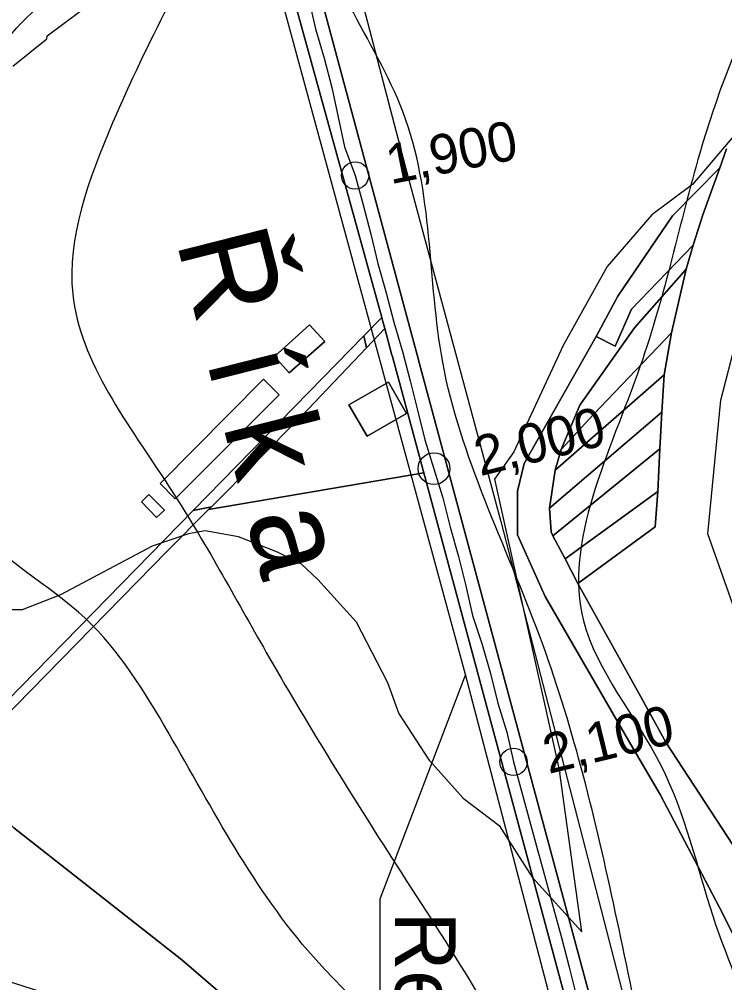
# Model space of a CAD drawing. Extents: x -510989 to -501240, y -1184665 to -1176098.
# Drawn here: x -504846 to -504613.7, y -1181469.7 to -1181152.6 of the extents above; entities that cross this region are included whole.
import ezdxf

# ---------------------------------------------------------------- set-up
doc = ezdxf.new("R2010")
doc.units = 0
for name, color, linetype in [('NAVRH_revitalizace_toku', 7, 'Continuous'), ('orna_puda', 7, 'Continuous'), ('ostatni_plocha_x_draha', 7, 'Continuous'), ('ostatni_plocha_x_jina_plocha', 7, 'Continuous'), ('ostatni_plocha_x_ostatni_komunikace', 7, 'Continuous'), ('ostatni_plocha_x_sportoviste_a_rekr_plocha', 7, 'Continuous'), ('STAV_zaplavove_uzemi', 7, 'Continuous'), ('trasovani_toku', 7, 'Continuous'), ('vodni_plocha_x_vodni_tok_v_koryt_prir_n_upr', 7, 'Continuous'), ('vrstevnice_01', 7, 'Continuous'), ('vrstevnice_02', 7, 'Continuous'), ('zastavena_plocha_a_nadvori', 7, 'Continuous')]:
    doc.layers.add(name, color=color, linetype=linetype)

msp = doc.modelspace()

# ---------------------------------------------------------------- linework, layer by layer
at = {"layer": 'NAVRH_revitalizace_toku'}
for points in [[(-504182.04, -1180792.04), (-504204.87, -1180813.12), (-504441.3, -1180893.49), (-504535.64, -1180920.73), (-504547.6, -1180927.38), (-504622.01, -1180977.87), (-504664.53, -1181014.41), (-504691.11, -1181051.62), (-504730.92, -1181097.66), (-504738.16, -1181127.41), (-504718.87, -1181201.36), (-504687.51, -1181317.93), (-504646.6, -1181475.99), (-504595.04, -1181660.81)], [(-504619.38, -1181665.94), (-504652.45, -1181546.29), (-504699.14, -1181368.28), (-504767.85, -1181115.82)], [(-504699.14, -1181368.28), (-504727.32, -1181442.23), (-504727.15, -1181617.42)]]:
    msp.add_lwpolyline(points, dxfattribs=at)
at = {"layer": 'orna_puda'}
for points in [[(-504609.62, -1181654.37), (-504714.66, -1181264.33), (-504714.68, -1181264.25), (-504716.76, -1181256.52), (-504751.58, -1181127.22), (-504752.67, -1181115.82), (-504749.63, -1181100.59), (-504733.91, -1181066.63), (-504677.14, -1181000.88), (-504645.58, -1180971.03), (-504557.05, -1180910.28)], [(-504613.13, -1181195.22), (-504615.31, -1181201.45), (-504630.96, -1181217.3), (-504648.9, -1181243.78), (-504656.11, -1181257), (-504679.79, -1181298.82), (-504681.95, -1181307.89), (-504681.99, -1181322.34), (-504672.85, -1181342.61), (-504645.47, -1181389.98), (-504634.98, -1181407.71), (-504614.42, -1181447.03), (-504604.62, -1181466.71)], [(-504604.62, -1181466.71), (-504614.42, -1181447.03), (-504634.98, -1181407.71), (-504645.47, -1181389.98), (-504672.85, -1181342.61), (-504681.99, -1181322.34), (-504681.95, -1181307.89), (-504679.79, -1181298.82), (-504656.11, -1181257), (-504649.83, -1181260.24), (-504644.42, -1181248.07), (-504624.08, -1181226.97), (-504626.48, -1181234.83), (-504643.41, -1181254.13), (-504661.43, -1181279.57), (-504667.62, -1181294.22), (-504669.52, -1181300.97), (-504671.47, -1181313.52), (-504670.91, -1181321.27), (-504670.38, -1181322.61), (-504666.3, -1181330.17), (-504662.07, -1181338.33), (-504641.94, -1181374.66), (-504633.05, -1181390.72), (-504607.29, -1181430.02)], [(-504833.48, -1181474.49), (-504875.32, -1181461.1), (-504900.47, -1181432.41), (-504866.87, -1181398.49), (-504862.77, -1181403.54), (-504857.98, -1181408.64), (-504847.86, -1181418.69), (-504792.48, -1181462.19), (-504731.58, -1181514.6)]]:
    msp.add_lwpolyline(points, dxfattribs=at)
for points in [[(-504615.31, -1181201.45), (-504620.93, -1181217), (-504624.08, -1181226.97), (-504644.42, -1181248.07), (-504649.83, -1181260.24), (-504656.11, -1181257), (-504648.9, -1181243.78), (-504630.96, -1181217.3)], [(-504626.48, -1181234.83), (-504631.24, -1181255.86), (-504657.03, -1181282.77), (-504667.62, -1181294.22), (-504661.43, -1181279.57), (-504643.41, -1181254.13)], [(-504725.66, -1181254.39), (-504723.31, -1181263.13), (-504723.29, -1181263.22), (-504721.2, -1181270.94), (-504712.86, -1181301.83), (-504783.7, -1181313.99), (-504782.76, -1181313.04), (-504753.12, -1181283.2), (-504731.68, -1181260.7)], [(-504631.24, -1181255.86), (-504633.68, -1181269.68), (-504669.52, -1181300.97), (-504667.62, -1181294.22), (-504657.03, -1181282.77)], [(-504737.48, -1181279.46), (-504731.51, -1181289.87), (-504718.49, -1181282.4), (-504724.47, -1181271.99)], [(-504633.68, -1181269.68), (-504634.41, -1181281.92), (-504671.47, -1181313.52), (-504669.52, -1181300.97)], [(-504634.41, -1181281.92), (-504635.12, -1181294), (-504670.38, -1181322.61), (-504670.91, -1181321.27), (-504671.47, -1181313.52)], [(-504635.12, -1181294), (-504635.8, -1181308), (-504666.3, -1181330.17), (-504670.38, -1181322.61)], [(-504783.7, -1181313.99), (-504712.86, -1181301.83), (-504662.52, -1181488.46), (-504731.58, -1181514.6), (-504792.48, -1181462.19), (-504847.86, -1181418.69), (-504857.98, -1181408.64), (-504862.77, -1181403.54), (-504866.87, -1181398.49), (-504866.31, -1181397.92), (-504864.53, -1181396.11), (-504862.24, -1181393.77), (-504797.28, -1181327.66)], [(-504635.8, -1181308), (-504636.64, -1181319.66), (-504662.07, -1181338.33), (-504666.3, -1181330.17)]]:
    msp.add_lwpolyline(points, close=True, dxfattribs=at)
at = {"layer": 'ostatni_plocha_x_draha'}
msp.add_lwpolyline([(-504607.29, -1181430.02), (-504633.05, -1181390.72), (-504641.94, -1181374.66), (-504662.07, -1181338.33), (-504636.64, -1181319.66), (-504635.8, -1181308), (-504635.12, -1181294), (-504634.41, -1181281.92), (-504633.68, -1181269.68), (-504631.24, -1181255.86), (-504626.48, -1181234.83), (-504624.08, -1181226.97), (-504620.93, -1181217), (-504615.31, -1181201.45), (-504613.13, -1181195.22)], dxfattribs=at)
at = {"layer": 'ostatni_plocha_x_jina_plocha'}
msp.add_lwpolyline([(-504737.48, -1181279.46), (-504724.47, -1181271.99), (-504718.49, -1181282.4), (-504731.51, -1181289.87)], close=True, dxfattribs=at)
at = {"layer": 'ostatni_plocha_x_ostatni_komunikace'}
for points in [[(-504726.28, -1181252.1), (-504725.66, -1181254.39), (-504731.68, -1181260.7), (-504732.57, -1181256.77), (-504726.66, -1181250.72)], [(-504731.68, -1181260.7), (-504753.12, -1181283.2), (-504782.76, -1181313.04), (-504788.79, -1181314.23), (-504750.73, -1181275.38), (-504732.57, -1181256.77)], [(-504783.7, -1181313.99), (-504797.28, -1181327.66), (-504862.24, -1181393.77), (-504864.28, -1181391.38), (-504788.79, -1181314.23), (-504782.76, -1181313.04)]]:
    msp.add_lwpolyline(points, close=True, dxfattribs=at)
at = {"layer": 'ostatni_plocha_x_sportoviste_a_rekr_plocha'}
msp.add_lwpolyline([(-504760.66, -1181127.46), (-504726.66, -1181250.72), (-504732.57, -1181256.77), (-504750.73, -1181275.38), (-504788.79, -1181314.23), (-504864.28, -1181391.38), (-504904.47, -1181432.44), (-504902.62, -1181434.58), (-504905.19, -1181437.02), (-504905.4, -1181440.61), (-504905.46, -1181441.72), (-504910.13, -1181446.83), (-504925.8, -1181463.98), (-504930.57, -1181459.1), (-505050.59, -1181336.35), (-504986.52, -1181183.63), (-504982.43, -1181174.23), (-504959.56, -1181157.6), (-504852.19, -1181115.81)], dxfattribs=at)
for points in [[(-504745.4, -1181258.63), (-504750.41, -1181253.22), (-504761.95, -1181263.61), (-504757.11, -1181269.01)], [(-504760.5, -1181276.22), (-504765.62, -1181271.1), (-504799.58, -1181305.39), (-504794.66, -1181310.46)], [(-504805.8, -1181311.48), (-504800.88, -1181316.62), (-504798.2, -1181314.14), (-504803.33, -1181308.99)]]:
    msp.add_lwpolyline(points, close=True, dxfattribs=at)
at = {"layer": 'STAV_zaplavove_uzemi'}
for points in [[(-504594.17, -1181642.09), (-504629.77, -1181535.28), (-504650.39, -1181443.46), (-504674.75, -1181355.39), (-504706.6, -1181265.44), (-504719.72, -1181182.99), (-504747.83, -1181113.66), (-504727.29, -1181064.42), (-504683.65, -1181020.77), (-504624.52, -1180967.28), (-504575.24, -1180927.85), (-504544.27, -1180915.18), (-504445.72, -1180881.39), (-504404.89, -1180867.31), (-504292.26, -1180829.3), (-504179.63, -1180791.29), (-504099.38, -1180734.98), (-504020.54, -1180698.37), (-503957.18, -1180675.84), (-503893.83, -1180664.58), (-503865.67, -1180678.66), (-503817.8, -1180689.92), (-503788.24, -1180689.92), (-503764.3, -1180695.55), (-503736.15, -1180687.11), (-503717.85, -1180698.37), (-503716.44, -1180708.23)], [(-502250.32, -1184002.61), (-502355.07, -1183875.41), (-502442.37, -1183790.61), (-502477.29, -1183700.82), (-502532.16, -1183578.61), (-502567.08, -1183448.91), (-502626.05, -1183402.34), (-502705.41, -1183380.59), (-502814.2, -1183349.87), (-502882.03, -1183297.39), (-502931.95, -1183237.24), (-503042.02, -1183107.97), (-503139.64, -1183018.94), (-503222.14, -1182957.59), (-503308.56, -1182839.96), (-503316.24, -1182784.92), (-503330.32, -1182756.77), (-503348.24, -1182719.65), (-503334.16, -1182651.82), (-503323.92, -1182595.5), (-503313.68, -1182526.39), (-503294.1, -1182480.5), (-503251.86, -1182396.03), (-503229.34, -1182314.37), (-503216.1, -1182227.15), (-503242.43, -1182174.5), (-503271.86, -1182129.59), (-503287.34, -1182081.58), (-503343.88, -1182028.1), (-503361.79, -1182008.91), (-503396.35, -1181952.59), (-503442.43, -1181933.39), (-503497.46, -1181888.6), (-503525.62, -1181860.44), (-503528.18, -1181837.4), (-503548.66, -1181767.01), (-503558.9, -1181729.89), (-503576.82, -1181682.53), (-503578.1, -1181621.1), (-503567.86, -1181572.46), (-503552.5, -1181536.63), (-503538.04, -1181458.36), (-503518.33, -1181411.9), (-503509.88, -1181341.51), (-503497.21, -1181207.63), (-503499.77, -1181097.56), (-503498.02, -1181031.35), (-503510.82, -1180970.85), (-503549.22, -1180952.23), (-503571.32, -1180940.6), (-503605.07, -1180937.11), (-503651.61, -1180939.44), (-503671.39, -1180917.33), (-503679.53, -1180892.89), (-503713.27, -1180871.95), (-503727.24, -1180859.15), (-503734.22, -1180833.55), (-503728.4, -1180799.81), (-503741.2, -1180770.72), (-503722.82, -1180725.17), (-503721.54, -1180703.41), (-503731.78, -1180697.01), (-503767.61, -1180699.57), (-503790.65, -1180697.01), (-503817.53, -1180697.01), (-503861.04, -1180686.77), (-503889.2, -1180675.25), (-503900.72, -1180668.85), (-503953.2, -1180679.09), (-503997.99, -1180697.01), (-504063.27, -1180722.61), (-504109.34, -1180749.49), (-504142.62, -1180776.36), (-504177.18, -1180796.84), (-504211.73, -1180817.32), (-504414.98, -1180961.5), (-504472.7, -1180998.11), (-504544.51, -1181068.5), (-504600.82, -1181143.12), (-504621.94, -1181196.62), (-504641.65, -1181267.01), (-504660.25, -1181350.62), (-504634.7, -1181398.32), (-504617.66, -1181447.72), (-504600.62, -1181492.01), (-504587, -1181548.23), (-504592.11, -1181628.29), (-504569.96, -1181682.81), (-504568.26, -1181664.07), (-504554.63, -1181621.48), (-504547.82, -1181597.63)], [(-504826.46, -1182247.73), (-504827.62, -1182204.68), (-504817.15, -1182165.12), (-504791.55, -1182113.93), (-504727.56, -1182034.81), (-504708.94, -1182017.35), (-504669.38, -1181991.76), (-504649.6, -1181961.5), (-504628.66, -1181917.29), (-504601.9, -1181867.26), (-504597.24, -1181809.08), (-504585.16, -1181766.79), (-504596.8, -1181741.4), (-504604.2, -1181726.59), (-504633.82, -1181658.9), (-504646.51, -1181600.72), (-504660.26, -1181556.29), (-504751.04, -1181459.08), (-504798.4, -1181384.84), (-504826.55, -1181347.73), (-504862.39, -1181315.73), (-504866.23, -1181265.81), (-504862.39, -1181205.66), (-504853.43, -1181164.7), (-504793.92, -1181116.47), (-504755.84, -1181064.64), (-504725.17, -1181018.1), (-504649.01, -1180947.23), (-504594, -1180900.69), (-504545.35, -1180879.53), (-504377.38, -1180832.83), (-504317.01, -1180808.36), (-504368.93, -1180802.59), (-504426.63, -1180826.63), (-504542.02, -1180859.32)], [(-504777.81, -1181111.78), (-504815.29, -1181186.74), (-504828.41, -1181242.96), (-504796.55, -1181306.67), (-504764.69, -1181361.01), (-504723.47, -1181428.47), (-504674.75, -1181510.92), (-504648.51, -1181582.13), (-504622.28, -1181672.07)]]:
    msp.add_spline(points, degree=3, dxfattribs=at)
at = {"layer": 'trasovani_toku'}
for p, q in [((-504750.71, -1181146.04), (-504748.53, -1181155.8)), ((-504748.53, -1181155.8), (-504745.65, -1181165.38)), ((-504745.65, -1181165.38), (-504743.16, -1181175.06)), ((-504743.16, -1181175.06), (-504740.99, -1181184.83)), ((-504740.99, -1181184.83), (-504738.96, -1181194.62)), ((-504738.96, -1181194.62), (-504735.46, -1181203.99)), ((-504735.46, -1181203.99), (-504732.82, -1181213.63)), ((-504732.82, -1181213.63), (-504730.24, -1181223.29)), ((-504730.24, -1181223.29), (-504727.94, -1181233.03)), ((-504727.94, -1181233.03), (-504725.21, -1181242.64)), ((-504725.21, -1181242.64), (-504722.64, -1181252.31)), ((-504722.64, -1181252.31), (-504719.82, -1181261.9)), ((-504719.82, -1181261.9), (-504717.32, -1181271.59)), ((-504717.32, -1181271.59), (-504714.88, -1181281.28)), ((-504714.88, -1181281.28), (-504712.54, -1181291)), ((-504712.54, -1181291), (-504709.47, -1181300.52)), ((-504709.47, -1181300.52), (-504706.61, -1181310.1)), ((-504706.61, -1181310.1), (-504704.11, -1181319.79)), ((-504704.11, -1181319.79), (-504701.42, -1181329.42)), ((-504701.42, -1181329.42), (-504698.97, -1181339.12)), ((-504698.97, -1181339.12), (-504696.79, -1181348.87)), ((-504696.79, -1181348.87), (-504693.66, -1181358.37)), ((-504693.66, -1181358.37), (-504690.81, -1181367.96)), ((-504690.81, -1181367.96), (-504688.41, -1181377.66)), ((-504688.41, -1181377.66), (-504685.53, -1181387.24)), ((-504685.53, -1181387.24), (-504683.29, -1181396.99)), ((-504683.29, -1181396.99), (-504680.61, -1181406.62)), ((-504680.61, -1181406.62), (-504677.97, -1181416.26)), ((-504677.97, -1181416.26), (-504675.38, -1181425.92)), ((-504675.38, -1181425.92), (-504672.71, -1181435.56)), ((-504672.71, -1181435.56), (-504670.16, -1181445.23)), ((-504670.16, -1181445.23), (-504667.51, -1181454.87)), ((-504667.51, -1181454.87), (-504664.94, -1181464.54)), ((-504664.94, -1181464.54), (-504662.53, -1181474.24))]:
    msp.add_line(p, q, dxfattribs=at)
for centre, radius in [((-504735.46, -1181203.99), 4.5), ((-504709.47, -1181300.52), 5.25), ((-504683.29, -1181396.99), 4.5)]:
    msp.add_circle(centre, radius, dxfattribs=at)
at = {"layer": 'vodni_plocha_x_vodni_tok_v_koryt_prir_n_upr'}
for points in [[(-504608.12, -1181659.96), (-504614.86, -1181665.13), (-504632.61, -1181599.34), (-504645.61, -1181551.13), (-504655.26, -1181515.38), (-504662.52, -1181488.46), (-504712.86, -1181301.83), (-504721.2, -1181270.94), (-504723.29, -1181263.22), (-504723.31, -1181263.13), (-504725.66, -1181254.39), (-504726.28, -1181252.1), (-504726.66, -1181250.72), (-504760.66, -1181127.46), (-504762.01, -1181115.76), (-504759.3, -1181101.6), (-504742.72, -1181064.52), (-504687.23, -1180996.05), (-504653.08, -1180963.75), (-504566.19, -1180904.56)], [(-504557.05, -1180910.28), (-504645.58, -1180971.03), (-504677.14, -1181000.88), (-504733.91, -1181066.63), (-504749.63, -1181100.59), (-504752.67, -1181115.82), (-504751.58, -1181127.22), (-504716.76, -1181256.52), (-504714.68, -1181264.25), (-504714.66, -1181264.33), (-504609.62, -1181654.37)]]:
    msp.add_lwpolyline(points, dxfattribs=at)
at = {"layer": 'vrstevnice_01'}
for points in [[(-504848.19, -1181168), (-504836.91, -1181159), (-504836.81, -1181158), (-504765.59, -1181105)], [(-504610.69, -1181191), (-504624.31, -1181207), (-504637.69, -1181217), (-504652.41, -1181234), (-504666.91, -1181260), (-504683.19, -1181295), (-504689.5, -1181304), (-504668.06, -1181400.59)], [(-504710.84, -1181396.73), (-504721, -1181381), (-504724.69, -1181371), (-504735, -1181351), (-504747.69, -1181337), (-504753.09, -1181332), (-504761, -1181328), (-504773.81, -1181323), (-504784.81, -1181321), (-504790.31, -1181322), (-504802.31, -1181326), (-504832.5, -1181342), (-504845.09, -1181347), (-504851.19, -1181347)], [(-504710.84, -1181396.73), (-504699.81, -1181409), (-504688, -1181418), (-504677.19, -1181435), (-504660.81, -1181453), (-504668.06, -1181400.59)]]:
    msp.add_lwpolyline(points, dxfattribs=at)
at = {"layer": 'vrstevnice_02'}
msp.add_lwpolyline([(-504588.91, -1181407.73), (-504619.31, -1181322), (-504615, -1181278), (-504604.69, -1181238)], dxfattribs=at)
at = {"layer": 'zastavena_plocha_a_nadvori'}
for points in [[(-504745.4, -1181258.63), (-504757.11, -1181269.01), (-504761.95, -1181263.61), (-504750.41, -1181253.22)], [(-504760.5, -1181276.22), (-504794.66, -1181310.46), (-504799.58, -1181305.39), (-504765.62, -1181271.1)], [(-504805.8, -1181311.48), (-504803.33, -1181308.99), (-504798.2, -1181314.14), (-504800.88, -1181316.62)]]:
    msp.add_lwpolyline(points, close=True, dxfattribs=at)

# ---------------------------------------------------------------- texts
at = {"layer": 'NAVRH_revitalizace_toku'}
msp.add_text('Revitalizace toku', height=20, rotation=270, dxfattribs=at).set_placement((-504722.32, -1181446.36))
at = {"layer": 'trasovani_toku'}
for s, height, rotation, p in [('1,900', 13, 11.2618, (-504723.81, -1181206.94)), ('Ř í k a', 30, 284.2265, (-504794.36, -1181225.62)), ('2,000', 13, 14.0419, (-504694.29, -1181303.03)), ('2,100', 13, 13.7964, (-504671.73, -1181401.03))]:
    msp.add_text(s, height=height, rotation=rotation, dxfattribs=at).set_placement(p)

doc.saveas('drawing.dxf')
